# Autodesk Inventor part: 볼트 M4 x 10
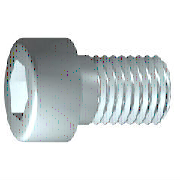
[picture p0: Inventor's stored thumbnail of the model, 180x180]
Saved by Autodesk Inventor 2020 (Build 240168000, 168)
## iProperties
IsCustomPart: 0
Created: 2012-02
Part Number: 볼트 M4 x 10
Material: 강철, 연강
Description: 6각 소켓 머리 캡 나사
Document SubType Name: Modeling
Standard: ISO 4762
Designer: mduedu
Standard Revision: Fourth edition 2004-03-01
Standards Organization: ISO
Language: ko-KR
Size Designation: M4 x 12
Categories: <MemberInstance><Categories><Category DisplayName="조임쇠" InternalName="e4da775c-781d-43d5-af7c-5136215cf5a6" Mnemonic="FSTN"><Category DisplayName="볼트" InternalN
Density: 7.75 g/cm^3
Appearance: 강철
Author: mduedu
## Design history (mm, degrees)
sketch "스케치1"
  geometry: L1 (-1, 0)-(10, 0); L2 (10, 0)-(10, 2); L3 (10, 2)-(1.75, 2); L4 (1.75, 2)-(1.32, 2); L5 (1.32, 2)-(0, 2); L6 (0, 2)-(0, 3.5); L7 (0, 3.5)-(-4, 3.5); L8 (-4, 3.5)-(-4, 1.732); L9 (-4, 1.732)-(-2, 1.732); L10 (-2, 1.732)-(-1, 0); L11 (-7.2, 0)-(15.2, 0) reference; L12 (0, -0.7)-(0, 4.2) reference; L13 (1.75, 2)-(0, 2)
  constraints: 22 end point, 6 parallel, 2 collinear, 2 perpendicular, 1 horizontal, 1 point on line
  dimensions: "d1" = 8.25 distance from line of L3.end L2 (= GEL); "d2" = 0.42952 distance of L4.end L3.end (computed from GAL); "d3" = 4 distance between parallel lines of L8 L6 (= KOH); "d4" = 2 distance of L8.end L9.end (= INTI); "d5" = 60 deg angle of L10 L1; "d6" = 4 diameter of L3 L1 (= GD); "d7" = 4 diameter of L5 L1 (= BDM); "d8" = 3.4641 diameter of L9 L1 (= 1.1547 x SW); "d9" = 7 diameter of L7 L1 (= KOD); "d26" = 10 distance between parallel lines of L12 L2 (= NLG)
revolve "본체" sketch "스케치1" stored, may be unused: angle "d10" = 90 deg
sketch "스케치2"
  geometry: L1 (0, -4.9)-(0, 4.9) reference; L2 (-4.9, 0)-(4.9, 0) reference; L3 (1.732, 0)-(0.866, -1.5); L4 (0.866, -1.5)-(-0.866, -1.5); L5 (-0.866, -1.5)-(-1.732, 0); L6 (-1.732, 0)-(-0.866, 1.5); L7 (-0.866, 1.5)-(0.866, 1.5); L8 (0.866, 1.5)-(1.732, 0); 2 further points
  constraints: 12 end point, 1 coincident, 1 horizontal alignment, 1 point on line, 12 other
extrude "슬롯" join sketch "스케치2" stored distance "d11" = 10; taper "d12" = 0 deg
workplane "Work Plane1"
fillet "Fillet2" dims "d30" = 0.1 (= R)
body "Solid1"
fillet "모깎기1" dims "d17" = 0.4 (= RR)
feature "스레드" dims "d13" = 8.25 (= GEL), "d14" = 0
chamfer "모따기1" distance "d15" = 0.42941 (= -0.5 x SPD + 0.5 x GD); stored, may be unused: second distance "d16" = 0.42941 (= GUL), angle "d27" = 45 deg
other parameters: "GD" = 4 [user parameter; used in 2 equation terms], "NLG" = 10 [user parameter; used in 1 equation term], "GEL" = 8.25 [user parameter; used in 2 equation terms], "KOD" = 7 [user parameter; used in 1 equation term], "KOH" = 4 [user parameter; used in 1 equation term], "INTI" = 2 [user parameter; used in 1 equation term], "GAL" = 0.42941 (= 0.61345 x PTC) [user parameter; used in 1 equation term], "GUL" = 0.42941 (= 0.61345 x PTC) [user parameter; used in 1 equation term], "BDM" = 4 (= NND) [user parameter; used in 1 equation term], "SW" = 3 [user parameter; used in 2 equation terms], "RR" = 0.4 [user parameter; used in 1 equation term], "SPD" = 3.14117 (= NND - 1.2269 x PTC) [user parameter; used in 1 equation term], "d19" = 0, "d28" = 0, "d29" = 0, "R" = 0.1 [user parameter; used in 1 equation term], "TOA" = 30 deg [user parameter], "GD1" = 3.14117 (= THREADDIA - 1.2269 x PTC) [user parameter], "THREADDIA" = 4 [user parameter; used in 1 equation term], "FAWI" = 45 deg [user parameter], "TPU" = 14.28571 (computed from PTC) [user parameter], "PTC" = 0.7 [user parameter; used in 5 equation terms], "NND" = 4 [user parameter; used in 2 equation terms], "E0" = 3.465 (= 1.155 x SW) [user parameter]
